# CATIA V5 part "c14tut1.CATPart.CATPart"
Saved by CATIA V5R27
Part number: Part1
Bounding box of the stored display mesh (mm): x 0 to 46, y -104 to 104, z 0 to 68
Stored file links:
  E:\_Deepak\2017_Deepak\CATIA\Resources\Tutorial Files\Tutorials\c14_catia_v5_6r2016_tut\c14tut1\c14tut1.CATPart.CATPart
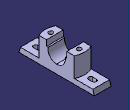
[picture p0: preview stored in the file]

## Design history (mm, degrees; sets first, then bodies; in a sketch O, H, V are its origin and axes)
Body1 (main body)
  Sketch1 on yz-plane, origin (0, 0, 0), H (0, 1, 0), V (0, 0, 1)
    axis line L1 (0, -39.4814) -> (0, 63.0107)
    point P1 (0, -39.4814)
    line L2 (0, 0) -> (104, 0)
    point P3 (104, 0)
    line L3 (104, 0) -> (100, 14)
    point P4 (100, 14)
    line L4 (100, 14) -> (54, 14)
    point P5 (54, 14)
    line L5 (54, 14) -> (54, 68)
    point P6 (54, 68)
    line L6 (54, 68) -> (28, 68)
    point P7 (28, 68)
    line L7 (28, 68) -> (28, 52)
    point P8 (28, 52)
    line L8 (28, 52) -> (23.6643, 52)
    point P9 (23.6643, 52)
    arc A1 centre (0, 48) radius 24 from (23.6643, 52) to (0, 24) cw
    point P10 (0, 48)
    point P11 (0, 24)
    point P12 (-104, 0)
    point P13 (0, 0)
    line L9 (0, 0) -> (-104, 0)
    point P14 (0, 24)
    point P15 (-23.6643, 52)
    point P16 (0, 48)
    arc A2 centre (0, 48) radius 24 from (-23.6643, 52) to (0, 24) ccw
    point P17 (-54, 68)
    point P18 (-28, 68)
    point P19 (-28, 52)
    line L10 (-54, 68) -> (-28, 68)
    line L11 (-28, 68) -> (-28, 52)
    line L12 (-28, 52) -> (-23.6643, 52)
    point P20 (-54, 14)
    line L13 (-54, 14) -> (-54, 68)
    point P21 (-100, 14)
    line L14 (-100, 14) -> (-54, 14)
    line L15 (-104, 0) -> (-100, 14)
    distance P3 P12 = 208
    length L3 V = 14
    distance L5 L13 = 108
    distance P18 P7 = 56
    distance P19 P18 = 16
    distance P15 P16 V = 4
    length L15 H = 4
    radius A1 = 24
    distance L6 L2 = 68
    coincidence: P1 V, P10 L1, L1 P11, O P13, P11 P14
    vertical: L1 V, L5 V, L7 V
    horizontal: L2 H, L4 H, L6 H, L8 H
    symmetry: P3 P12 L1, O P13 L1, L2 L9 L1, P11 P14 L1, P9 P15 L1, A1 A2 L1, P6 P17 L1, P7 P18 L1, P8 P19 L1, L6 L10 L1, L7 L11 L1, L8 L12 L1, P5 P20 L1, L5 L13 L1, P4 P21 L1, L4 L14 L1, L3 L15 L1
  Pad1: profile Sketch1, direction (1, 0, 0), length 46
  Sketch2 on face of Pad1, origin (0, 0, 14), H (1, 0, 0), V (0, 1, 0)
    arc A1 centre (23, 4) radius 50 from (0, 48.3959) to (46, 48.3959) cw
    point P2 (0, 48.3959)
    point P3 (46, 48.3959)
    reference projected line E1 (46, 54) -> (46, 28) from edge [face of Pad1 | face of Pad1]
    construction line L1 (46, 48.3959) -> (0, 48.3959)
    reference projected line E2 (0, 54) -> (46, 54) from edge [face of Pad1 | face of Pad1]
    axis line L2 (-10.6771, 0) -> (51.171, 0)
    point P4 (-10.6771, 0)
    point P6 (46, -48.3959)
    point P7 (0, -48.3959)
    arc A2 centre (23, -4) radius 50 from (0, -48.3959) to (46, -48.3959) ccw
    line L3 (0, -48.3959) -> (0, 48.3959)
    line L4 (46, 48.3959) -> (46, -48.3959)
    radius A1 = 50
    coincidence: P2 V, P3 E1, P4 H
    horizontal: L1 H, L2 H
    tangency: A1 E2
    symmetry: P3 P6 L2, P2 P7 L2, A1 A2 L2
    vertical: L3 V, L4 V
  Pocket1: profile Sketch2, direction (0, 0, 1), through (limit type 3), outer side
  Sketch3 on face of Pad1 from Sketch1.L9, origin (0, 0, 0), H (1, 0, 0), V (0, -1, 0)
    point P1 (23, 39)
    line L1 (36, 52) -> (36, 26)
    line L2 (36, 26) -> (10, 26)
    line L3 (10, 26) -> (10, 52)
    line L4 (10, 52) -> (36, 52)
    reference intersected line E1 (0, 104) -> (46, 104) from face of Pad1
    reference projected line E2 (0, 104) -> (0, 0) from edge [start face of Pad1 | face of Pad1 from Sketch1.L9]
    length L3 = 26
    length L4 = 26
    distance L2 E1 = 78
    distance L3 E2 = 10
    vertical: L1 V, L3 V
    horizontal: L2 H, L4 H
    equidistance: L1 L3 P1, L2 L4 P1
  Pocket2: profile Sketch3, direction (0, 0, 1), length 10
  Sketch4 on face of Pad1, origin (24.629, 46.0353, 68), H (1, 0, 0), V (0, 1, 0)
    point P1 (-1.629, -85.0353)
    axis line L1 (11.371, -98.0353) -> (-14.629, -72.0353)
    point P2 (11.371, -98.0353)
    point P3 (-14.629, -72.0353)
    reference projected point E1 (11.371, -98.0353) from vertex [face of Pocket2 | face of Pocket2 | face of Pocket2]
    reference projected point E2 (-14.629, -72.0353) from vertex [face of Pocket2 | face of Pocket2 | face of Pocket2]
    coincidence: P2 E1, P3 E2
    midpoint: P1 L1
  Hole1: placed by Sketch4, at (23, -39, 68) direction (0, 0, -1), diameter 12, depth 100, V-bottom angle 120
  Sketch5 on face of Pad1, origin (0, 0, 14), H (1, 0, 0), V (0, 1, 0)
    construction line L1 (23, -71) -> (23, -81)
    point P2 (23, -81)
    line L2 (29, -71) -> (29, -81)
    line L3 (17, -81) -> (17, -71)
    arc A1 centre (23, -81) radius 6 from (29, -81) to (17, -81) cw
    arc A2 centre (23, -71) radius 6 from (17, -71) to (29, -71) cw
    reference projected line E1 (46, -54) -> (46, -100) from edge of Pad1
    reference projected line E2 (0, -104) -> (46, -104) from edge [face of Pad1 | face of Pad1]
    distance L1 E1 = 23
    distance P2 E2 = 23
    radius A1 = 6
    length L1 = 10
    vertical: L1 V
    tangency: A1 L2, A2 L2, A1 L3, A2 L3
    parallelism: L1 L2
  Pocket3: profile Sketch5, direction (0, 0, -1), through (limit type 3)
  Mirror1: of Pocket2, Hole1, Pocket3, about zx-plane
